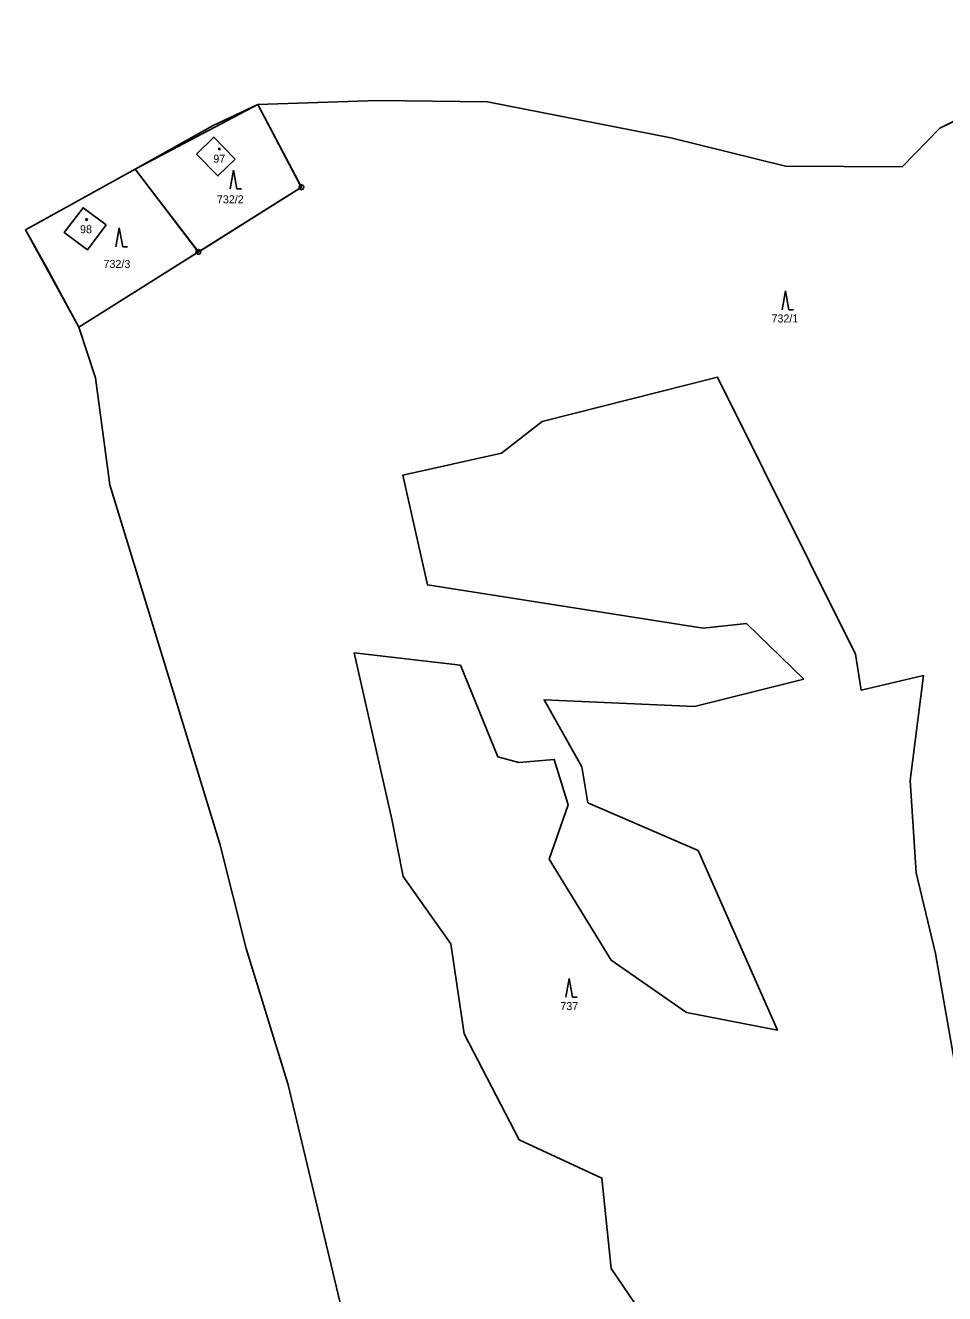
# Model space of a CAD drawing. Extents: x -760642 to -757221, y -1092371 to -1088855.
# Drawn here: x -760520.2 to -760325, y -1090939.2 to -1090669.8 of the extents above; entities that cross this region are included whole.
import ezdxf

# ---------------------------------------------------------------- set-up
doc = ezdxf.new("R2010")
doc.units = 0
for name, color, linetype in [('Vrstva 1', 7, 'Continuous'), ('Vrstva 13', 7, 'Continuous'), ('Vrstva 18', 7, 'Continuous'), ('Vrstva 19', 7, 'Continuous'), ('Vrstva 24', 7, 'Continuous'), ('Vrstva 25', 7, 'Continuous'), ('Vrstva 28', 7, 'Continuous'), ('Vrstva 30', 7, 'Continuous')]:
    doc.layers.add(name, color=color, linetype=linetype)

msp = doc.modelspace()

# ---------------------------------------------------------------- linework, layer by layer
at = {"layer": 'Vrstva 1'}
for p, q in [((-760461.63, -1090704.22), (-760470.84, -1090686.68)), ((-760483.9, -1090697.17), (-760480.23, -1090693.56)), ((-760475.69, -1090698.28), (-760480.23, -1090693.56)), ((-760483.9, -1090697.17), (-760479.34, -1090701.84)), ((-760479.34, -1090701.84), (-760475.69, -1090698.28)), ((-760483.51, -1090717.98), (-760496.95, -1090700.39)), ((-760483.51, -1090717.98), (-760461.63, -1090704.22)), ((-760507.98, -1090708.6), (-760512.02, -1090713.84)), ((-760507.98, -1090708.6), (-760503.1, -1090712.23)), ((-760507.04, -1090717.52), (-760503.1, -1090712.23)), ((-760507.04, -1090717.52), (-760512.02, -1090713.84)), ((-760508.9, -1090733.95), (-760483.51, -1090717.98)), ((-760410.47, -1090753.99), (-760373.27, -1090744.57)), ((-760373.27, -1090744.57), (-760343.96, -1090803.38)), ((-760419.09, -1090760.69), (-760410.47, -1090753.99)), ((-760440.05, -1090765.39), (-760419.09, -1090760.69)), ((-760440.05, -1090765.39), (-760434.85, -1090788.71)), ((-760434.85, -1090788.71), (-760376.31, -1090797.87)), ((-760376.31, -1090797.87), (-760367.06, -1090796.88)), ((-760367.06, -1090796.88), (-760354.94, -1090808.69)), ((-760450.41, -1090803.14), (-760427.83, -1090805.76)), ((-760450.41, -1090803.14), (-760442.38, -1090838.45)), ((-760343.96, -1090803.38), (-760342.75, -1090811.03)), ((-760427.83, -1090805.76), (-760419.88, -1090825.2)), ((-760342.75, -1090811.03), (-760329.52, -1090807.96)), ((-760329.52, -1090807.96), (-760332.3, -1090830.25)), ((-760354.94, -1090808.69), (-760378.12, -1090814.51)), ((-760378.12, -1090814.51), (-760410.06, -1090813.1)), ((-760410.06, -1090813.1), (-760402.03, -1090827.34)), ((-760419.88, -1090825.2), (-760415.44, -1090826.4)), ((-760415.44, -1090826.4), (-760407.91, -1090825.78)), ((-760407.91, -1090825.78), (-760404.95, -1090835.4)), ((-760402.03, -1090827.34), (-760400.75, -1090834.97)), ((-760332.3, -1090830.25), (-760331.06, -1090849.88)), ((-760400.75, -1090834.97), (-760377.35, -1090845.14)), ((-760404.95, -1090835.4), (-760408.97, -1090846.99)), ((-760442.38, -1090838.45), (-760440.03, -1090850.67)), ((-760377.35, -1090845.14), (-760360.53, -1090883.3)), ((-760408.97, -1090846.99), (-760395.86, -1090868.41)), ((-760440.03, -1090850.67), (-760429.86, -1090864.95)), ((-760331.06, -1090849.88), (-760326.96, -1090866.97)), ((-760429.86, -1090864.95), (-760427.03, -1090884.07)), ((-760326.96, -1090866.97), (-760322.2, -1090894.14)), ((-760395.86, -1090868.41), (-760379.82, -1090879.53)), ((-760379.82, -1090879.53), (-760360.53, -1090883.3)), ((-760427.03, -1090884.07), (-760415.4, -1090906.56)), ((-760415.4, -1090906.56), (-760397.78, -1090914.69)), ((-760397.78, -1090914.69), (-760395.84, -1090933.92)), ((-760395.84, -1090933.92), (-760390.7, -1090941.4))]:
    msp.add_line(p, q, dxfattribs=at)
at = {"layer": 'Vrstva 13'}
for p, q in [((-760470.84, -1090686.68), (-760480.37, -1090691.15)), ((-760445.38, -1090685.84), (-760470.84, -1090686.68)), ((-760445.38, -1090685.84), (-760422.1, -1090686.12)), ((-760422.1, -1090686.12), (-760383.18, -1090693.74)), ((-760325.99, -1090691.71), (-760312.01, -1090684.77)), ((-760480.37, -1090691.15), (-760496.95, -1090700.39)), ((-760333.99, -1090699.87), (-760325.99, -1090691.71)), ((-760383.18, -1090693.74), (-760358.8, -1090699.76)), ((-760358.8, -1090699.76), (-760333.99, -1090699.87)), ((-760496.95, -1090700.39), (-760520.25, -1090713.3)), ((-760520.25, -1090713.3), (-760515.72, -1090721.35)), ((-760515.72, -1090721.35), (-760508.9, -1090733.95)), ((-760508.9, -1090733.95), (-760505.34, -1090744.7)), ((-760505.34, -1090744.7), (-760502.31, -1090767.43)), ((-760502.31, -1090767.43), (-760480.32, -1090839.29)), ((-760480.32, -1090839.29), (-760478.97, -1090843.69)), ((-760478.97, -1090843.69), (-760473.37, -1090865.91)), ((-760473.37, -1090865.91), (-760464.43, -1090894.9)), ((-760464.43, -1090894.9), (-760448.69, -1090960.8))]:
    msp.add_line(p, q, dxfattribs=at)
at = {"layer": 'Vrstva 24'}
for centre, radius in [((-760461.63, -1090704.22), 0.5), ((-760461.63, -1090704.22), 0.0327), ((-760483.51, -1090717.98), 0.5), ((-760483.51, -1090717.98), 0.0327)]:
    msp.add_circle(centre, radius, dxfattribs=at)
at = {"layer": 'Vrstva 25'}
for p, q in [((-760476.052, -1090700.569), (-760476.785, -1090704.569)), ((-760476.052, -1090700.569), (-760475.319, -1090704.569)), ((-760475.319, -1090704.569), (-760474.319, -1090704.569)), ((-760500.302, -1090712.879), (-760501.035, -1090716.879)), ((-760500.302, -1090712.879), (-760499.569, -1090716.879)), ((-760499.569, -1090716.879), (-760498.569, -1090716.879)), ((-760358.802, -1090726.249), (-760359.535, -1090730.249)), ((-760358.802, -1090726.249), (-760358.069, -1090730.249)), ((-760358.069, -1090730.249), (-760357.069, -1090730.249)), ((-760404.752, -1090872.309), (-760405.485, -1090876.309)), ((-760404.752, -1090872.309), (-760404.019, -1090876.309)), ((-760404.019, -1090876.309), (-760403.019, -1090876.309))]:
    msp.add_line(p, q, dxfattribs=at)
for centre in [(-760479.05, -1090696.1), (-760507.25, -1090711.09)]:
    msp.add_circle(centre, 0.175, dxfattribs=at)
at = {"layer": 'Vrstva 28'}
msp.add_lwpolyline([(-760448.69, -1090960.8), (-760464.43, -1090894.9), (-760473.37, -1090865.91), (-760478.97, -1090843.69), (-760502.31, -1090767.43), (-760505.34, -1090744.7), (-760508.9, -1090733.95), (-760520.25, -1090713.3), (-760496.95, -1090700.39), (-760470.84, -1090686.68), (-760445.38, -1090685.84), (-760422.1, -1090686.12), (-760383.18, -1090693.74), (-760358.8, -1090699.76), (-760333.99, -1090699.87), (-760325.99, -1090691.71), (-760312.01, -1090684.77), (-760309.98, -1090673.67), (-760311.93, -1090653.88)], dxfattribs=at)
at = {"layer": 'Vrstva 30'}
for points in [[(-760461.862, -1090703.777), (-760470.84, -1090686.68), (-760496.95, -1090700.39), (-760483.814, -1090717.583)], [(-760281.574, -1090886.32), (-760255.71, -1090849.28), (-760261.87, -1090840.05), (-760277.14, -1090810.8), (-760286.18, -1090784.42), (-760292.14, -1090767.45), (-760299.59, -1090751.55), (-760290.16, -1090697.58), (-760312.01, -1090684.77), (-760325.99, -1090691.71), (-760333.99, -1090699.87), (-760358.8, -1090699.76), (-760383.18, -1090693.74), (-760422.1, -1090686.12), (-760445.38, -1090685.84), (-760470.84, -1090686.68), (-760461.862, -1090703.777)], [(-760475.69, -1090698.28), (-760480.23, -1090693.56), (-760483.9, -1090697.17), (-760479.34, -1090701.84), (-760475.69, -1090698.28)], [(-760483.814, -1090717.583), (-760496.95, -1090700.39), (-760520.25, -1090713.3), (-760515.72, -1090721.35), (-760508.9, -1090733.95), (-760483.933, -1090718.246)], [(-760483.087, -1090717.714), (-760462.053, -1090704.486)], [(-760462.053, -1090704.486), (-760483.087, -1090717.714)], [(-760503.1, -1090712.23), (-760507.98, -1090708.6), (-760512.02, -1090713.84), (-760507.04, -1090717.52), (-760503.1, -1090712.23)], [(-760483.933, -1090718.246), (-760508.9, -1090733.95), (-760505.34, -1090744.7), (-760502.31, -1090767.43), (-760480.317, -1090839.289), (-760478.97, -1090843.69), (-760473.37, -1090865.91), (-760464.43, -1090894.9), (-760448.69, -1090960.8), (-760408.07, -1090970.88), (-760375.23, -1090971.94), (-760345.74, -1090970.01), (-760339.59, -1090969.86), (-760334.08, -1090970.89), (-760331.955, -1090967.831)], [(-760390.7, -1090941.4), (-760395.84, -1090933.92), (-760397.78, -1090914.69), (-760415.4, -1090906.56), (-760427.03, -1090884.07), (-760429.86, -1090864.95), (-760440.03, -1090850.67), (-760442.38, -1090838.45), (-760450.41, -1090803.14), (-760427.83, -1090805.76), (-760419.88, -1090825.2), (-760415.44, -1090826.4), (-760407.91, -1090825.78), (-760404.95, -1090835.4), (-760408.97, -1090846.99), (-760395.86, -1090868.41), (-760379.82, -1090879.53), (-760360.53, -1090883.3), (-760377.35, -1090845.14), (-760400.75, -1090834.97), (-760402.03, -1090827.34), (-760410.06, -1090813.1), (-760378.12, -1090814.51), (-760354.94, -1090808.69), (-760367.06, -1090796.88), (-760376.31, -1090797.87), (-760434.85, -1090788.71), (-760440.05, -1090765.39), (-760419.09, -1090760.69), (-760410.47, -1090753.99), (-760373.27, -1090744.57), (-760343.96, -1090803.38), (-760342.75, -1090811.03), (-760329.52, -1090807.96), (-760332.3, -1090830.25), (-760331.06, -1090849.88), (-760326.96, -1090866.97), (-760322.2, -1090894.14)], [(-760322.2, -1090894.14), (-760326.96, -1090866.97), (-760331.06, -1090849.88), (-760332.3, -1090830.25), (-760329.52, -1090807.96), (-760342.75, -1090811.03), (-760343.96, -1090803.38), (-760373.27, -1090744.57), (-760410.47, -1090753.99), (-760419.09, -1090760.69), (-760440.05, -1090765.39), (-760434.85, -1090788.71), (-760376.31, -1090797.87), (-760367.06, -1090796.88), (-760354.94, -1090808.69), (-760378.12, -1090814.51), (-760410.06, -1090813.1), (-760402.03, -1090827.34), (-760400.75, -1090834.97), (-760377.35, -1090845.14), (-760360.53, -1090883.3), (-760379.82, -1090879.53), (-760395.86, -1090868.41), (-760408.97, -1090846.99), (-760404.95, -1090835.4), (-760407.91, -1090825.78), (-760415.44, -1090826.4), (-760419.88, -1090825.2), (-760427.83, -1090805.76), (-760450.41, -1090803.14), (-760442.38, -1090838.45), (-760440.03, -1090850.67), (-760429.86, -1090864.95), (-760427.03, -1090884.07), (-760415.4, -1090906.56), (-760397.78, -1090914.69), (-760395.84, -1090933.92), (-760390.7, -1090941.4)]]:
    msp.add_lwpolyline(points, dxfattribs=at)
for centre, start, end in [((-760461.63, -1090704.22), 117.70331, 180), ((-760461.63, -1090704.22), 180, 212.16516), ((-760461.63, -1090704.22), 212.16516, 0), ((-760461.63, -1090704.22), 0, 117.70331), ((-760483.51, -1090717.98), 127.38238, 180), ((-760483.51, -1090717.98), 180, 212.16939), ((-760483.51, -1090717.98), 212.16939, 0), ((-760483.51, -1090717.98), 32.16516, 127.38238), ((-760483.51, -1090717.98), 0, 32.16516)]:
    msp.add_arc(centre, 0.5, start, end, dxfattribs=at)

# ---------------------------------------------------------------- texts
at = {"layer": 'Vrstva 18'}
for s, p in [('732/2', (-760479.57, -1090707.65)), ('732/3', (-760503.65, -1090721.37)), ('732/1', (-760361.768, -1090732.96)), ('737', (-760406.62, -1090879.02))]:
    msp.add_text(s, height=1.7, dxfattribs=at).set_placement(p)
at = {"layer": 'Vrstva 19'}
for s, p in [('97', (-760480.33, -1090699.02)), ('98', (-760508.64, -1090714))]:
    msp.add_text(s, height=1.7, dxfattribs=at).set_placement(p)

doc.saveas('drawing.dxf')
